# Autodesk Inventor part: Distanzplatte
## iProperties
Created: 2007-04
Part Number: Distanzplatte
Document SubType Name: Modeling
Designer: Benno
Manufacturer: Standard
Standards Organization: Custom
Author: Benno
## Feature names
1. Extrusion1
2. Fase1 [Chamfer]
3. Bohrung1 [Hole]
4. Fase2 [Chamfer]
5. Fase3 [Chamfer]
6. Fase4 [Chamfer]
7. Rundung1 [Fillet]
